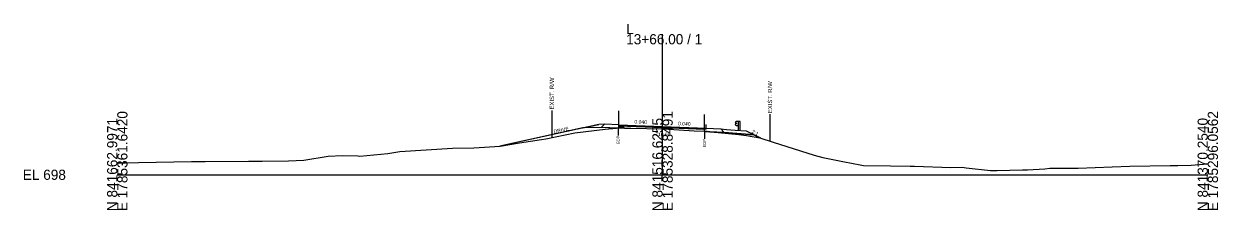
# Model space of a CAD drawing. Extents: x -26 to 5203, y -10 to 9576.
# Drawn here: x 3574.3 to 3902.8, y -9.7 to 41.4 of the extents above; entities that cross this region are included whole.
import ezdxf

# ---------------------------------------------------------------- set-up
doc = ezdxf.new("R2010")
doc.units = 0
for name, color, linetype in [('Exist Cross Section Cell', 7, 'Continuous'), ('Exist XS Center Line Elevation Label', 7, 'Continuous'), ('Exist XS Ground Line', 7, 'Continuous'), ('Old_Level_10', 7, 'Continuous'), ('Prop XS Earthwork Shape', 7, 'Continuous'), ('Prop XS EOT Tick Mark', 7, 'Continuous'), ('Prop XS Finish Grade', 7, 'Continuous'), ('Prop XS Finish Grade Earthwork', 7, 'Continuous'), ('Prop XS Finish Grade Paved Shoulder', 7, 'Continuous'), ('Prop XS Finish Grade Pavement', 7, 'Continuous'), ('Prop XS Guardrail', 7, 'Continuous'), ('Prop XS Hydro Fill Slope Data', 7, 'Continuous'), ('Prop XS Pvmt Edge Slope', 7, 'Continuous'), ('Prop XS SE Text', 7, 'Continuous'), ('Prop XS Side Slope Text', 7, 'Continuous'), ('Prop XS Subgrade Earthwork', 7, 'Continuous'), ('Scratch_Level_4', 7, 'Continuous'), ('Scratch_Level_6', 7, 'Continuous')]:
    doc.layers.add(name, color=color, linetype=linetype)

msp = doc.modelspace()

# ---------------------------------------------------------------- linework, layer by layer
at = {"layer": 'Exist Cross Section Cell'}
for p, q in [((3750, 0), (3750, 38.62)), ((3600, 0), (3750, 0)), ((3750, 0), (3900, 0))]:
    msp.add_line(p, q, dxfattribs=at)
at = {"layer": 'Exist XS Ground Line'}
msp.add_lwpolyline([(3600, 3.27), (3602.3, 3.3), (3605.83, 3.33), (3620.41, 3.63), (3621.03, 3.65), (3621.47, 3.65), (3624.22, 3.67), (3636.14, 3.75), (3639.9, 3.77), (3647.09, 3.86), (3651.32, 3.99), (3658.01, 5.07), (3661.97, 5.3), (3666.14, 5.17), (3666.74, 5.12), (3674.46, 5.82), (3677.72, 6.38), (3692.2, 7.26), (3698.09, 7.39), (3705.31, 7.88), (3710.61, 8.76), (3716.66, 9.65), (3717.9, 9.88), (3725.88, 11.53), (3734.25, 12.52), (3737.82, 12.87), (3737.89, 12.85), (3741.26, 12.79), (3750, 12.6), (3750.28, 12.6), (3758.74, 12.09), (3761.61, 11.93), (3765.28, 11.58), (3771.01, 11.09), (3773.08, 10.74), (3776.77, 10.1), (3780.47, 8.91), (3791.68, 5.37), (3794.12, 4.71), (3800.52, 3.42), (3801.48, 3.29), (3805.31, 2.56), (3812.7, 2.45), (3818.14, 2.39), (3819.32, 2.36), (3829.31, 1.97), (3832.45, 2.06), (3833.5, 1.92), (3840.21, 1.13), (3842.1, 1.17), (3848.99, 1.31), (3850.37, 1.32), (3855.18, 1.64), (3856.56, 1.77), (3858.13, 1.8), (3864.35, 1.83), (3873.69, 2.2), (3878.52, 2.36), (3889.65, 2.54), (3891.76, 2.58), (3895.42, 2.68), (3898.85, 2.93), (3900, 3.09)], dxfattribs=at)
at = {"layer": 'Old_Level_10'}
for p, q in [((3719.56, 17.62), (3719.56, 10.22)), ((3779.56, 16.61), (3779.56, 9.21)), ((3737.8, 12.87), (3737.8, 10.82)), ((3761.53, 11.94), (3761.53, 9.89))]:
    msp.add_line(p, q, dxfattribs=at)
at = {"layer": 'Prop XS Earthwork Shape'}
for points in [[(3728.09, 12.89), (3705.2, 7.87), (3705.31, 7.88), (3710.61, 8.76), (3716.66, 9.65), (3717.9, 9.88), (3725.88, 11.53), (3734.25, 12.52), (3737.34, 12.82), (3733.12, 12.99)], [(3737.34, 12.82), (3737.82, 12.87), (3737.89, 12.85), (3738, 12.85), (3738, 12.8)], [(3761.53, 11.94), (3761.53, 11.86), (3761.96, 11.84), (3763.03, 11.8), (3761.61, 11.93)], [(3763.03, 11.8), (3765.28, 11.58), (3771.01, 11.09), (3773.08, 10.74), (3776.77, 10.1), (3777.04, 10.01), (3775.09, 10.99), (3766.96, 11.64)]]:
    msp.add_lwpolyline(points, close=True, dxfattribs=at)
at = {"layer": 'Prop XS EOT Tick Mark'}
for p, q in [((3738, 13.72), (3738, 14.72)), ((3762, 12.76), (3762, 13.76))]:
    msp.add_line(p, q, dxfattribs=at)
at = {"layer": 'Prop XS Finish Grade'}
for p, q in [((3728.09, 12.89), (3732.43, 13.84)), ((3734, 13.88), (3732.43, 13.84)), ((3766, 12.6), (3767.61, 12.47)), ((3767.61, 12.47), (3770, 12.28)), ((3770, 12.28), (3773, 12.04)), ((3773, 12.04), (3775.09, 10.99))]:
    msp.add_line(p, q, dxfattribs=at)
at = {"layer": 'Prop XS Finish Grade Earthwork'}
for p, q in [((3728.09, 12.89), (3705.2, 7.87)), ((3775.09, 10.99), (3777.04, 10.01))]:
    msp.add_line(p, q, dxfattribs=at)
at = {"layer": 'Prop XS Finish Grade Paved Shoulder'}
for p, q in [((3738, 13.72), (3734, 13.88)), ((3762, 12.76), (3766, 12.6))]:
    msp.add_line(p, q, dxfattribs=at)
at = {"layer": 'Prop XS Finish Grade Pavement'}
for p, q in [((3738, 13.72), (3750, 13.24)), ((3750, 13.24), (3762, 12.76))]:
    msp.add_line(p, q, dxfattribs=at)
at = {"layer": 'Prop XS Guardrail'}
for p, q in [((3770.03, 14.47), (3770, 14.41)), ((3770, 14.41), (3770.03, 14.35)), ((3770.03, 13.86), (3770, 13.8)), ((3770, 13.8), (3770.03, 13.74)), ((3770.32, 14.67), (3770.03, 14.47)), ((3770.03, 14.35), (3770.32, 14.15)), ((3770.32, 14.06), (3770.03, 13.86)), ((3770.03, 13.74), (3770.32, 13.54)), ((3770.82, 14.67), (3770.32, 14.67)), ((3770.32, 14.15), (3770.32, 14.06)), ((3770.32, 13.54), (3770.82, 13.54)), ((3770.82, 14.67), (3770.82, 12.17)), ((3771.32, 14.67), (3770.82, 14.67)), ((3771.32, 12.17), (3771.32, 14.67))]:
    msp.add_line(p, q, dxfattribs=at)
at = {"layer": 'Prop XS Hydro Fill Slope Data'}
for p, q in [((3732.43, 13.84), (3705.2, 7.87)), ((3773, 12.04), (3777.04, 10.01))]:
    msp.add_line(p, q, dxfattribs=at)
at = {"layer": 'Prop XS Pvmt Edge Slope'}
for p, q in [((3734, 13.88), (3733.12, 12.99)), ((3766, 12.6), (3766.96, 11.64))]:
    msp.add_line(p, q, dxfattribs=at)
at = {"layer": 'Prop XS Subgrade Earthwork'}
for p, q in [((3733.12, 12.99), (3728.09, 12.89)), ((3738, 12.8), (3733.12, 12.99)), ((3738, 12.85), (3738, 12.8)), ((3761.53, 11.94), (3761.53, 11.86)), ((3761.53, 11.86), (3761.96, 11.84)), ((3761.96, 11.84), (3766.96, 11.64)), ((3766.96, 11.64), (3775.09, 10.99))]:
    msp.add_line(p, q, dxfattribs=at)
at = {"layer": 'Scratch_Level_4'}
for p, q in [((3738, 12.85), (3738, 17.52)), ((3761.53, 11.94), (3761.53, 16.57)), ((3738, 13.59), (3750, 13.11)), ((3750, 13.11), (3762, 12.63))]:
    msp.add_line(p, q, dxfattribs=at)
at = {"layer": 'Scratch_Level_6'}
for p, q in [((3750, 13.11), (3738, 13.59)), ((3738, 13.59), (3738, 13.47)), ((3738, 13.47), (3750, 12.99)), ((3738, 13.47), (3750, 12.99)), ((3750, 12.99), (3738, 13.47)), ((3738, 13.47), (3738, 13.13)), ((3737.98, 13.13), (3739.26, 13.08)), ((3738, 13.13), (3739.26, 13.08)), ((3739.26, 13.08), (3738, 13.13)), ((3738, 13.13), (3738, 12.85)), ((3738, 12.85), (3739.5, 12.82)), ((3739.26, 13.08), (3739.5, 12.82)), ((3739.26, 13.08), (3739.5, 12.82)), ((3739.5, 12.82), (3739.26, 13.08)), ((3761.53, 12.65), (3750, 13.11)), ((3750, 12.99), (3762, 12.51)), ((3750, 12.99), (3761.53, 12.52)), ((3761.53, 12.52), (3750, 12.99)), ((3761.53, 12.52), (3761.53, 12.65)), ((3761.53, 11.94), (3761.53, 12.52))]:
    msp.add_line(p, q, dxfattribs=at)
msp.add_lwpolyline([(3739.5, 12.82), (3741.26, 12.79), (3750, 12.6), (3750.28, 12.6), (3758.74, 12.09), (3761.53, 11.94)], dxfattribs=at)

# ---------------------------------------------------------------- texts
at = {"layer": 'Exist Cross Section Cell'}
for s, p in [('L', (3740, 38.62)), ('13+66.00 / 1', (3740, 35.82)), ('EL 698', (3574, -1.4))]:
    msp.add_text(s, height=2.8, dxfattribs=at).set_placement(p)
for s, p in [('E 1785361.6420', (3602.8, -10)), ('E 1785328.8491', (3752.8, -10)), ('E 1785296.0562', (3902.8, -10)), ('N 841662.9971', (3600, -10)), ('N 841516.6255', (3750, -10)), ('N 841370.2540', (3900, -10))]:
    msp.add_text(s, height=2.8, rotation=90, dxfattribs=at).set_placement(p)
at = {"layer": 'Exist XS Center Line Elevation Label'}
msp.add_text('DRIVE', height=1, rotation=12.3721, dxfattribs=at).set_placement((3720.18, 11.32))
msp.add_text('710.60', height=1, dxfattribs=at).set_placement((3747.95, 10.6))
at = {"layer": 'Old_Level_10'}
for s, height, p in [('EXIST. R/W', 1.181, (3720.15, 17.92)), ('EXIST. R/W', 1.181, (3780.15, 16.91)), ('EOP', 0.787, (3738.19, 8.42)), ('EOP', 0.787, (3761.93, 7.49))]:
    msp.add_text(s, height=height, rotation=90, dxfattribs=at).set_placement(p)
at = {"layer": 'Prop XS SE Text'}
for p in [(3742.25, 14.05), (3754.25, 13.57)]:
    msp.add_text('0.040', height=1, rotation=357.7094, dxfattribs=at).set_placement(p)
at = {"layer": 'Prop XS Side Slope Text'}
msp.add_text('2:1', height=1, rotation=333.4349, dxfattribs=at).set_placement((3774.41, 11.53))

doc.saveas('drawing.dxf')
